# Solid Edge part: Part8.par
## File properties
Author: TIET
Template: Iso Metric Part.par
Last saved by: Ashutosh-CADCIM
Revision: 3
Application: Solid Edge
Accuracy: 0.990
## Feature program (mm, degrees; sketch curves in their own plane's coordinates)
sketch for "unnamed Protrusion 1" plane through (0, 0, 0) normal (0, 1, 0) x-axis (1, 0, 0)
  circle centre (0, 0) radius 87.1438
extrude "unnamed Protrusion 1" add finite 20.9072 along -normal
sketch for "ExtrudedProtrusion_2" #1 plane through (0, -20.9072, 0) normal (0, -1, 0) x-axis (1, 0, 0)
  circle centre (0, 0) radius 29.2182
sketch for "ExtrudedProtrusion_2" #2 plane through (0, -20.9072, 0) normal (0, -1, 0) x-axis (1, 0, 0)
  circle centre (0, 0) radius 42.9092
extrude "ExtrudedProtrusion_2" add finite 29.1638 along +normal
sketch for "ExtrudedCutout_1" plane through (0, -20.9072, 0) normal (0, -1, 0) x-axis (1, 0, 0)
  circle centre (0, 63.4817) radius 6.8014
extrude "ExtrudedCutout_1" cut finite 88.7737 along -normal
pattern "unnamed Pattern 1" of "ExtrudedCutout_1"
extrude "unnamed Cutout 1" cut finite 88.7737
extrude "unnamed Cutout 2" cut finite 88.7737
extrude "unnamed Cutout 3" cut finite 88.7737
extrude "unnamed Cutout 4" cut finite 88.7737
extrude "unnamed Cutout 5" cut finite 88.7737
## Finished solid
Body 1: solid body, 13 faces, 18 edges, 0 vertices.
  Faces by surface: cylinder 9, plane 4
  Edges by curve: circle 18
Bounding box of the edges (mm): 174.288 x 50.071 x 174.288, from (-87.1438, -50.071, -87.1438) to (87.1438, 0, 87.1438).
Cylindrical faces by radius (mm): R6.8014 x6, R29.2182 x1, R42.9092 x1, R87.1438 x1
Planar faces by outward normal: +y 1, -y 3
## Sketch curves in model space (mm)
circle centre (0, -20.9072, 63.4817) radius 6.8014
circle centre (0, -20.9072, 0) radius 42.9092
circle centre (0, -20.9072, 0) radius 29.2182
circle centre (0, 0, 0) radius 87.1438
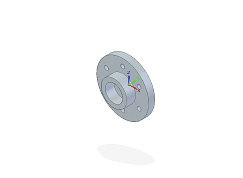
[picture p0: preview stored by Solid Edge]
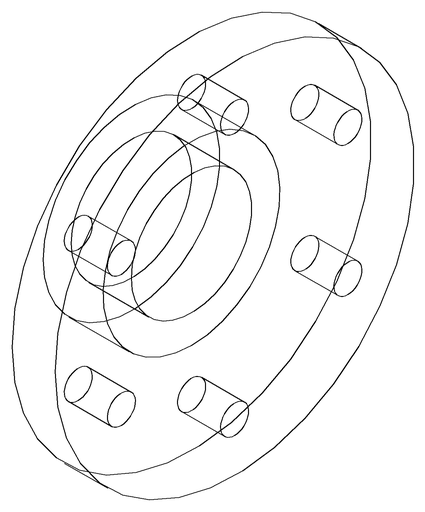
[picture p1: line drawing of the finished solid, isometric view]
